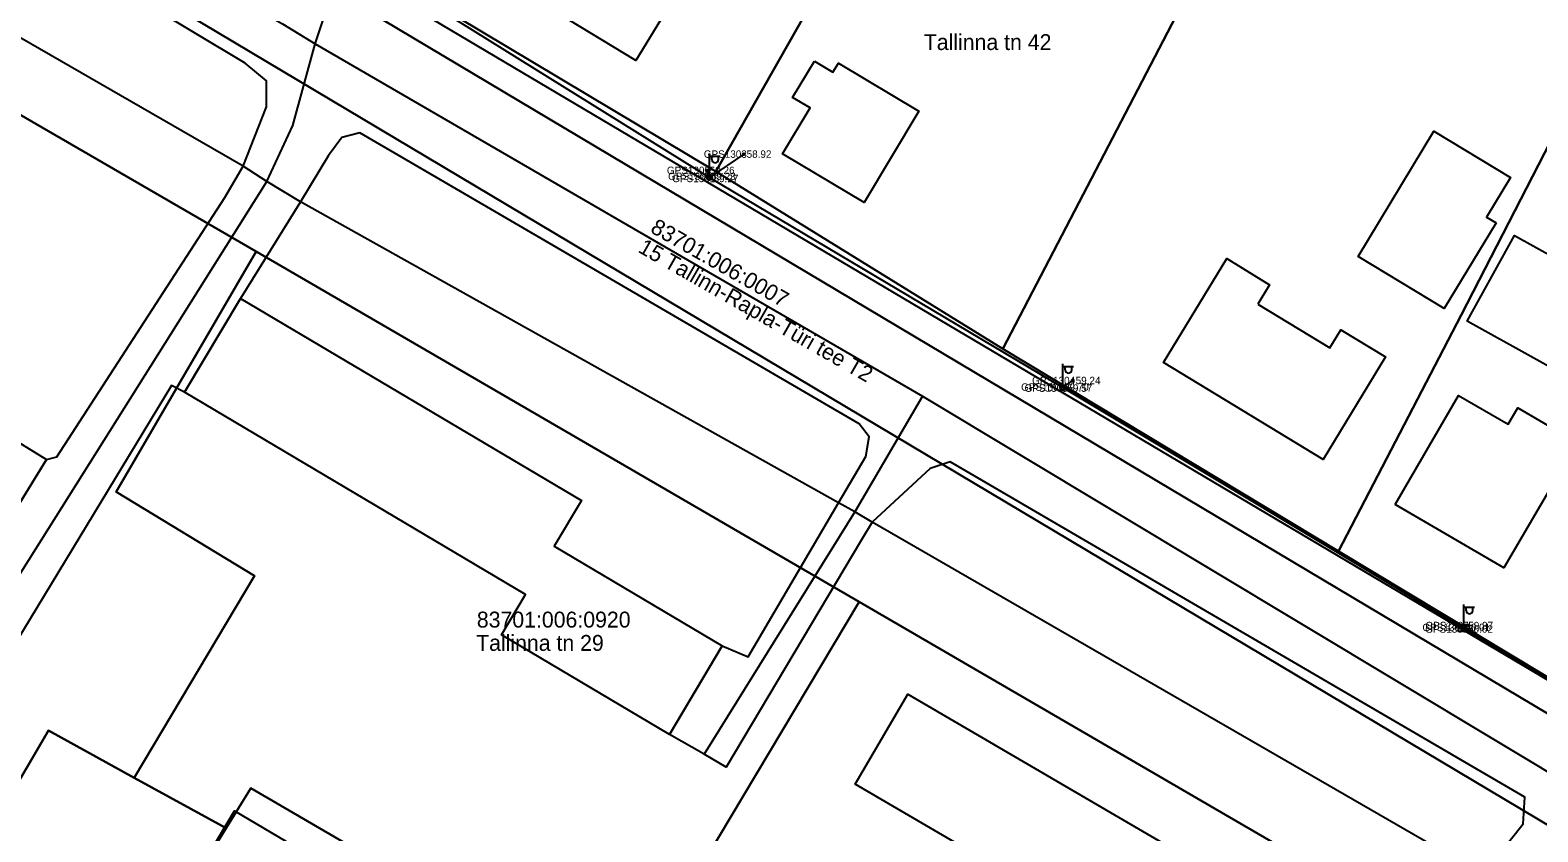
# Model space of a CAD drawing. Extents: x 580119 to 583377, y 6518915 to 6520820.
# Drawn here: x 581553.7 to 581695.9, y 6519827.6 to 6519903.3 of the extents above; entities that cross this region are included whole.
import ezdxf

# ---------------------------------------------------------------- set-up
doc = ezdxf.new("R2010")
doc.units = 0
for name, color, linetype in [('Hoone Elu- või ühiskondlik hoone', 7, 'Continuous'), ('Hoone Kõrval- või tootmishoone', 7, 'Continuous'), ('L_AADRESS', 7, 'Continuous'), ('MOOTKORG-EH2000', 7, 'Continuous'), ('MOOTMPUNKT', 7, 'Continuous'), ('MOOTNR', 7, 'Continuous'), ('MPOHULIIN', 7, 'Continuous'), ('PIIR', 7, 'Continuous'), ('POST', 7, 'Continuous'), ('SIOHULIIN', 7, 'Continuous'), ('SIRAJATIS', 7, 'Continuous'), ('Tee Kergliiklustee Püsikate', 7, 'Continuous'), ('Tee Liiklusala', 7, 'Continuous'), ('Tee Tugimaantee Püsikate', 7, 'Continuous'), ('Tee Tänav Püsikate', 7, 'Continuous'), ('TUNNUS', 7, 'Continuous')]:
    doc.layers.add(name, color=color, linetype=linetype)

msp = doc.modelspace()

# ---------------------------------------------------------------- linework, layer by layer
at = {"layer": 'Hoone Elu- või ühiskondlik hoone'}
for points in [[(581615.94, 6519908.78), (581610.86, 6519900.42), (581597.04, 6519908.83), (581602.12, 6519917.18)], [(581627.69, 6519900.35), (581629.44, 6519899.3), (581629.97, 6519900.17), (581637.55, 6519895.62), (581632.38, 6519887.01), (581624.69, 6519891.62), (581627.29, 6519895.94), (581625.63, 6519896.93)], [(581669.52, 6519877.42), (581676.33, 6519873.28), (581677.37, 6519874.99), (581681.58, 6519872.43), (581675.7, 6519862.74), (581660.62, 6519871.91), (581666.59, 6519881.72), (581670.64, 6519879.25)], [(581619, 6519845.16), (581614.04, 6519836.8), (581598.19, 6519846.21), (581600.45, 6519850.02), (581568.28, 6519869.1), (581573.54, 6519877.95), (581605.71, 6519858.87), (581603.15, 6519854.56)], [(581555.24, 6519862.76), (581537.58, 6519833.98), (581529.3, 6519839.06), (581546.95, 6519867.85)], [(581682.48, 6519858.51), (581688.47, 6519868.8), (581693.14, 6519866.08), (581694.04, 6519867.63), (581699.64, 6519864.37), (581692.74, 6519852.53)], [(581682.39, 6519808.48), (581677.26, 6519799.71), (581663.91, 6519807.5), (581661.32, 6519809.01), (581663.81, 6519813.26), (581663.37, 6519813.51), (581631.55, 6519832.09), (581636.52, 6519840.59), (581668.77, 6519821.75), (581666.45, 6519817.78)]]:
    msp.add_lwpolyline(points, close=True, dxfattribs=at)
at = {"layer": 'Hoone Kõrval- või tootmishoone'}
for points in [[(581692.01, 6519885.1), (581687.11, 6519876.99), (581678.98, 6519881.9), (581686.12, 6519893.74), (581693.35, 6519889.38), (581691.11, 6519885.64)], [(581706.9, 6519876.59), (581702.41, 6519868.51), (581689.26, 6519875.82), (581693.74, 6519883.9)], [(581572.33, 6519817.46), (581567.5, 6519820.33), (581572.99, 6519829.59), (581577.83, 6519826.72)]]:
    msp.add_lwpolyline(points, close=True, dxfattribs=at)
at = {"layer": 'MOOTMPUNKT'}
for centre in [(581621.04, 6519891.58), (581617.56, 6519890.04), (581617.67, 6519889.48), (581617.92, 6519889.28), (581652.08, 6519870.21), (581650.97, 6519869.59), (581651.3, 6519869.49), (581688.83, 6519846.9), (581689.1, 6519846.75), (581689.12, 6519847.08)]:
    msp.add_circle(centre, 0.1, dxfattribs=at)
at = {"layer": 'MPOHULIIN'}
for p, q in [((581651.14, 6519869.54), (581652.08, 6519870.21)), ((581688.96, 6519846.82), (581689.12, 6519847.08))]:
    msp.add_line(p, q, dxfattribs=at)
for points in [[(581386.07, 6520026.02), (581416.88, 6520008.2), (581446.3, 6519991.39), (581473.57, 6519975.61), (581504.78, 6519957.66), (581539.72, 6519936.99), (581580.34, 6519912.71), (581617.8, 6519889.38), (581651.14, 6519869.54), (581688.96, 6519846.82), (581727.78, 6519823.51), (581768.99, 6519798.83), (581799.65, 6519780), (581800.76, 6519769.03)], [(581621.04, 6519891.58), (581617.8, 6519889.38), (581617.56, 6519890.04)]]:
    msp.add_lwpolyline(points, dxfattribs=at)
at = {"layer": 'PIIR'}
for points in [[(581689.84, 6519815.63), (581631.91, 6519849.33), (581575.03, 6519882.38), (581543.14, 6519900.86), (581505.13, 6519922.94), (581483.99, 6519935.14), (581314, 6520033.36)], [(581761.13, 6519789.94), (581562.34, 6519908.5), (581363.85, 6520022.11), (581368.33, 6520029.92), (581566.91, 6519916.24), (581765.76, 6519797.71)], [(581765.76, 6519797.71), (581566.91, 6519916.24), (581368.33, 6520029.92)], [(581386.35, 6520025.87), (581417.16, 6520008.29), (581442.14, 6519993.86), (581446.53, 6519991.3), (581473.92, 6519975.28), (581505.33, 6519957.51), (581518.19, 6519949.74), (581546.98, 6519932.72), (581562.55, 6519923.42), (581578.78, 6519913.69), (581589.04, 6519907.54), (581618.38, 6519889.95), (581645.47, 6519873.21), (581677.12, 6519854.1), (581713.07, 6519832.45), (581720.83, 6519828.38), (581751.53, 6519809.56)], [(581385.98, 6520004.33), (581488.8, 6519942.86), (581562.34, 6519908.5), (581761.13, 6519789.94)]]:
    msp.add_lwpolyline(points, dxfattribs=at)
for points in [[(581668.17, 6519916.88), (581690.81, 6519960.49), (581722.2, 6519941.94), (581712.02, 6519921.66), (581700.49, 6519899.32), (581688.7, 6519876.39), (581677.12, 6519854.1), (581645.47, 6519873.21)], [(581614.48, 6519948.9), (581640.64, 6519933.67), (581642.55, 6519932.5), (581618.38, 6519889.95), (581589.04, 6519907.54)], [(581642.55, 6519932.5), (581668.17, 6519916.88), (581645.47, 6519873.21), (581618.38, 6519889.95)], [(581513.81, 6519802.22), (581530.13, 6519831.94), (581525.61, 6519842.75), (581530.57, 6519852.17), (581513.31, 6519861.5), (581517.49, 6519868.48), (581522.09, 6519865.67), (581529.63, 6519878.27), (581543.14, 6519900.86), (581575.03, 6519882.38), (581561.83, 6519859.69), (581574.89, 6519851.77), (581563.53, 6519832.71), (581555.45, 6519837.16), (581529.53, 6519792.85)], [(581688.7, 6519876.39), (581700.49, 6519899.32), (581737.53, 6519880.2), (581713.07, 6519832.45), (581677.12, 6519854.1)], [(581561.83, 6519859.69), (581575.03, 6519882.38), (581631.91, 6519849.33), (581608.97, 6519810.82), (581594.06, 6519818.04), (581594.93, 6519819.84), (581574.53, 6519831.74), (581572.2, 6519827.94), (581563.53, 6519832.71), (581574.89, 6519851.77)], [(581631.91, 6519849.33), (581689.84, 6519815.63), (581680.66, 6519799.67), (581667.91, 6519798.29), (581655.99, 6519805.27), (581650.4, 6519794.91), (581632.37, 6519804.68), (581630.43, 6519800.22), (581612.65, 6519809.04), (581608.97, 6519810.82)], [(581529.53, 6519792.85), (581555.45, 6519837.16), (581563.53, 6519832.71), (581572.2, 6519827.94), (581544.38, 6519782.68)], [(581572.2, 6519827.94), (581574.53, 6519831.74), (581594.93, 6519819.84), (581594.06, 6519818.04), (581569.92, 6519768.18), (581544.38, 6519782.68)]]:
    msp.add_lwpolyline(points, close=True, dxfattribs=at)
at = {"layer": 'POST'}
for p, q in [((581617.8, 6519889.63), (581617.8, 6519891.63)), ((581617.8, 6519891.38), (581618.8, 6519891.38)), ((581618.02, 6519891.06), (581618.02, 6519891.38)), ((581618.64, 6519891.06), (581618.64, 6519891.38)), ((581617.8, 6519889.38), (581617.8, 6519889.38)), ((581651.14, 6519869.79), (581651.14, 6519871.79)), ((581651.14, 6519871.54), (581652.14, 6519871.54)), ((581651.36, 6519871.22), (581651.36, 6519871.54)), ((581651.98, 6519871.22), (581651.98, 6519871.54)), ((581651.14, 6519869.54), (581651.14, 6519869.54)), ((581688.96, 6519847.07), (581688.96, 6519849.07)), ((581688.96, 6519848.82), (581689.96, 6519848.82)), ((581689.19, 6519848.5), (581689.19, 6519848.82)), ((581689.8, 6519848.5), (581689.8, 6519848.82)), ((581688.96, 6519846.82), (581688.96, 6519846.82))]:
    msp.add_line(p, q, dxfattribs=at)
for centre in [(581617.8, 6519889.38), (581651.14, 6519869.54), (581688.96, 6519846.82)]:
    msp.add_circle(centre, 0.25, dxfattribs=at)
for centre in [(581618.33, 6519891.06), (581651.67, 6519871.22), (581689.5, 6519848.5)]:
    msp.add_arc(centre, 0.306, 180, 0, dxfattribs=at)
at = {"layer": 'SIOHULIIN'}
msp.add_lwpolyline([(581504.78, 6519957.66), (581539.72, 6519936.99), (581580.34, 6519912.71), (581617.8, 6519889.38), (581651.14, 6519869.54), (581688.96, 6519846.82), (581727.78, 6519823.51), (581768.99, 6519798.83), (581799.65, 6519780)], dxfattribs=at)
at = {"layer": 'SIRAJATIS'}
msp.add_lwpolyline([(581688.46, 6519847.12), (581689.46, 6519847.12), (581689.46, 6519846.52), (581688.46, 6519846.52)], close=True, dxfattribs=at)
for centre, radius in [((581688.76, 6519846.82), 0.0304), ((581688.76, 6519846.82), 0.029), ((581688.76, 6519846.82), 0.0277), ((581688.76, 6519846.82), 0.0263), ((581688.76, 6519846.82), 0.0249), ((581688.76, 6519846.82), 0.0236), ((581688.76, 6519846.82), 0.0222), ((581688.76, 6519846.82), 0.0209), ((581688.76, 6519846.82), 0.0195), ((581688.76, 6519846.82), 0.0181), ((581688.76, 6519846.82), 0.0168), ((581688.76, 6519846.82), 0.0154), ((581688.76, 6519846.82), 0.014), ((581688.76, 6519846.82), 0.0127), ((581688.76, 6519846.82), 0.0113), ((581688.76, 6519846.82), 0.00996), ((581688.76, 6519846.82), 0.0086), ((581688.76, 6519846.82), 0.00724), ((581688.76, 6519846.82), 0.00587), ((581688.76, 6519846.82), 0.00451), ((581688.76, 6519846.82), 0.00315), ((581688.76, 6519846.82), 0.00179), ((581688.76, 6519846.82), 0.000426), ((581689.16, 6519846.82), 0.0304), ((581689.16, 6519846.82), 0.029), ((581689.16, 6519846.82), 0.0277), ((581689.16, 6519846.82), 0.0263), ((581689.16, 6519846.82), 0.0249), ((581689.16, 6519846.82), 0.0236), ((581689.16, 6519846.82), 0.0222), ((581689.16, 6519846.82), 0.0209), ((581689.16, 6519846.82), 0.0195), ((581689.16, 6519846.82), 0.0181), ((581689.16, 6519846.82), 0.0168), ((581689.16, 6519846.82), 0.0154), ((581689.16, 6519846.82), 0.014), ((581689.16, 6519846.82), 0.0127), ((581689.16, 6519846.82), 0.0113), ((581689.16, 6519846.82), 0.00996), ((581689.16, 6519846.82), 0.0086), ((581689.16, 6519846.82), 0.00724), ((581689.16, 6519846.82), 0.00587), ((581689.16, 6519846.82), 0.00451), ((581689.16, 6519846.82), 0.00315), ((581689.16, 6519846.82), 0.00179), ((581689.16, 6519846.82), 0.000426)]:
    msp.add_circle(centre, radius, dxfattribs=at)
at = {"layer": 'Tee Kergliiklustee Püsikate'}
for points in [[(581576.03, 6519888.98), (581573.8, 6519890.44), (581524.01, 6519919.17), (581503.69, 6519931.09), (581500.01, 6519933.13)], [(581631.5, 6519857.8), (581629.98, 6519858.65), (581579.22, 6519887.06), (581576.03, 6519888.98)], [(581695.09, 6519820.88), (581692.68, 6519822.38), (581690.76, 6519823.58), (581633.14, 6519856.85), (581631.5, 6519857.8)]]:
    msp.add_lwpolyline(points, dxfattribs=at)
at = {"layer": 'Tee Liiklusala'}
for points in [[(581696.81, 6520018.09), (581670.62, 6520033.41), (581664.28, 6520022.59), (581661.99, 6520024.22), (581658.18, 6520025.44), (581655.71, 6520024.82), (581651.36, 6520018.77), (581640.71, 6520000.46), (581611.85, 6519951.75), (581586.93, 6519909.16), (581588.4, 6519906.51), (581590.91, 6519904.75), (581712.97, 6519832.38)], [(581537.58, 6519833.98), (581555.24, 6519862.76), (581556.23, 6519863.01), (581572.07, 6519887.49), (581573.8, 6519890.44), (581576.02, 6519896.04), (581576.02, 6519898.49), (581574, 6519900.15), (581541.28, 6519919.76)], [(581690.76, 6519823.58), (581694.56, 6519828.37), (581694.72, 6519830.89), (581640.51, 6519862.53), (581638.62, 6519861.91), (581633.14, 6519856.85), (581632.15, 6519855.17), (581619.38, 6519833.7), (581617.28, 6519834.95), (581614.04, 6519836.8), (581619, 6519845.16), (581621.45, 6519844.14), (581629.98, 6519858.65), (581632.54, 6519863.02), (581632.85, 6519864.88), (581631.92, 6519866.11), (581584.81, 6519893.6), (581583.11, 6519893.14), (581581.87, 6519891.44), (581579.22, 6519887.06), (581573.54, 6519877.95), (581568.28, 6519869.1), (581567.06, 6519869.73), (581542.34, 6519828.95)]]:
    msp.add_lwpolyline(points, dxfattribs=at)
at = {"layer": 'Tee Tugimaantee Püsikate'}
for points in [[(581506.09, 6519944.2), (581577.51, 6519903.87), (581580.61, 6519901.98)], [(581580.61, 6519901.98), (581637.89, 6519868.72)], [(581637.89, 6519868.72), (581700.8, 6519830.9)]]:
    msp.add_lwpolyline(points, dxfattribs=at)
at = {"layer": 'Tee Tänav Püsikate'}
for points in [[(581580.61, 6519901.98), (581581.89, 6519905.86), (581608.45, 6519951.44), (581637.26, 6520000), (581641.12, 6520006.58), (581663.82, 6520044.98)], [(581576.03, 6519888.98), (581578.49, 6519894.28), (581580.61, 6519901.98)], [(581539.42, 6519830.74), (581576.03, 6519888.98)], [(581637.89, 6519868.72), (581631.5, 6519857.8)], [(581631.5, 6519857.8), (581617.28, 6519834.95)]]:
    msp.add_lwpolyline(points, dxfattribs=at)

# ---------------------------------------------------------------- texts
at = {"layer": 'L_AADRESS'}
for s, p in [('Tallinna tn 42', (581638.01, 6519901.4)), ('Tallinna tn 29', (581595.78, 6519844.69))]:
    msp.add_text(s, height=1.5, dxfattribs=at).set_placement(p)
msp.add_text('15 Tallinn-Rapla-Türi tee T2', height=1.5, rotation=330.2323, dxfattribs=at).set_placement((581610.97, 6519882.38))
at = {"layer": 'MOOTKORG-EH2000'}
for s, p in [(' 58.92', (581621.04, 6519891.23)), (' 59.26', (581617.56, 6519889.69)), (' 59.23', (581617.67, 6519889.13)), (' 59.27', (581617.92, 6519888.93)), (' 59.24', (581652.08, 6519869.86)), (' 59.70', (581650.97, 6519869.24)), (' 59.57', (581651.3, 6519869.14)), (' 60.01', (581688.83, 6519846.55)), (' 60.02', (581689.1, 6519846.4)), (' 59.97', (581689.12, 6519846.73))]:
    msp.add_text(s, height=0.7, dxfattribs=at).set_placement(p)
at = {"layer": 'MOOTNR'}
for s, p in [('GPS1303 ', (581617.26, 6519891.23)), ('GPS1302 ', (581613.78, 6519889.69)), ('GPS1300 ', (581613.89, 6519889.13)), ('GPS1301 ', (581614.28, 6519888.93)), ('GPS1304 ', (581648.23, 6519869.86)), ('GPS1306 ', (581647.19, 6519869.24)), ('GPS1305 ', (581647.52, 6519869.14)), ('GPS1308 ', (581685.05, 6519846.55)), ('GPS1309 ', (581685.32, 6519846.4)), ('GPS1307 ', (581685.34, 6519846.73))]:
    msp.add_text(s, height=0.7, dxfattribs=at).set_placement(p)
at = {"layer": 'TUNNUS'}
msp.add_text('83701:006:0007', height=1.5, rotation=330.2323, dxfattribs=at).set_placement((581612.12, 6519884.26))
msp.add_text('83701:006:0920', height=1.5, dxfattribs=at).set_placement((581595.85, 6519846.89))

doc.saveas('drawing.dxf')
